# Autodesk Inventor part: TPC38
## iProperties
Shininess: 64.0
Length Units: 11272
Angle Units: 11279
Time Units: 11290
Mass Units: 11286
Length Display Precision: 3
Angle Display Precision: 2
Compacted: True
Part Number: TPC38
Document SubType Name: Modeling
Created: 2004-08
Designer: Lori
Manufacturer: Standard
Standards Organization: Custom
Density: 0.0
Volumn: 0.0
Area: 0.0
PropertySet Name: Model Information
Control State: 0
Master: False
Checked Out: False
Author: Lori
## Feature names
1. Base1
